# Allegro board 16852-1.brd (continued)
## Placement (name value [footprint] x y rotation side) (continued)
C5542  SCD1U50V3KX-GP  [C603H36]  69.88 87.03 180 top
C5617  SCD01U50V2KX-1GP  [C402H22]  264.54 35.04 0 top
C5618  SCD01U50V2KX-1GP  [C402H22]  263.65 35.04 0 top
C5619  SCD01U50V2KX-1GP  [C402H22]  261.75 35.04 180 top
C5620  SCD01U50V2KX-1GP  [C402H22]  262.64 35.04 180 top
C5621  SC1U10V2KX-1GP  [C402H22]  261.11 29.2 90 bottom
C5622  SC1U10V2KX-1GP  [C402H22]  261.11 33.77 270 bottom
C5623  SC1U10V2KX-1GP  [C402H22]  265.18 32.62 90 bottom
C5701  SCD1U16V2KX-3GP  [C402H22]  22.61 68.57 90 bottom
C5702  SCD1U16V2KX-3GP  [C402H22]  17.4 79.61 90 top
C5703  SCD1U16V2KX-3GP  [C402H22]  22.61 69.45 90 bottom
C5704  SCD1U16V2KX-3GP  [C402H22]  22.61 67.68 90 bottom
C5705  SCD1U16V2KX-3GP  [C402H22]  22.43 65.29 90 bottom
C5706  SCD1U16V2KX-3GP  [C402H22]  22.43 66.18 90 bottom
C5707  SCD1U16V2KX-3GP  [C402H22]  22.43 64.27 90 bottom
C5708  SCD1U16V2KX-3GP  [C402H22]  22.43 63.38 90 bottom
C5709  SCD1U16V2KX-3GP  [C402H22]  22.61 70.34 90 bottom
C5710  SCD1U16V2KX-3GP  [C402H22]  17.4 78.73 90 top
C6001  SCD1U16V2KX-3GP  [C402H22]  258.7 30.47 0 bottom
C6002  SC10U6D3V3MX-GP  [C603H38]  258.44 25.77 0 top
C6003  SCD01U50V2KX-1GP  [C402H22]  262 26.15 0 top
C6004  SCD01U50V2KX-1GP  [C402H22]  262.89 26.15 0 top
C6005  SCD01U50V2KX-1GP  [C402H22]  263.78 26.15 0 top
C6006  SCD01U50V2KX-1GP  [C402H22]  264.67 26.15 0 top
C6007  SCD1U16V2KX-3GP  [C402H22]  259.71 19.87 270 top
C6008  SC4D7U6D3V3KX-GP  [C603H36]  259.59 21.8 270 top
C6009  SC4D7U6D3V3KX-GP  [C603H36]  259.59 23.07 270 top
C6010  SCD1U16V2KX-3GP  [C402H22]  246.76 23.99 0 bottom
C6011  SC10U6D3V3MX-GP  [C603H38]  247.27 21.58 180 bottom
C6012  SCD1U16V2KX-3GP  [C402H22]  248.59 16.9 90 bottom
C6013  SC4D7U6D3V3KX-GP  [C603H36]  248.41 18.02 90 bottom
C6014  SC4D7U6D3V3KX-GP  [C603H36]  248.41 19.42 90 bottom
C6107  SCD1U16V2KX-3GP  [C402H22]  36.63 51.57 270 top
C6108  SC4D7U6D3V3KX-GP  [C603H36]  46.71 58.51 0 top
C6109  SCD1U16V2KX-3GP  [C402H22]  37.39 65.8 270 top
C6110  SC470P50V2KX-3GP  [C402H22]  37.39 66.69 270 top
C6111  SC470P50V2KX-3GP  [C402H22]  36.63 50.68 270 top
C6112  SC10U6D3V3MX-GP  [C603H38]  45.44 58.51 0 top
C6113  SC2200P50V2KX-2GP  [C402H22]  47.73 63.23 180 top
C6201  SCD1U16V2KX-3GP  [C402H22]  94.23 124.98 180 top
C6202  SCD1U16V2KX-3GP  [C402H22]  93.34 124.98 180 top
C6203  SCD1U16V2KX-3GP  [C402H22]  89.74 102.78 180 top
C6204  SCD1U16V2KX-3GP  [C402H22]  98.04 117.76 90 top
C6205  SCD1U16V2KX-3GP  [C402H22]  98.04 116.88 90 top
C6206  SC2200P50V2KX-2GP  [C402H22]  89.74 107.55 180 top
C6207  SCD1U16V2KX-3GP  [C402H22]  100.58 113.4 90 top
C6208  SCD1U16V2KX-3GP  [C402H22]  100.58 112.51 90 top
C6306  SC22P50V2JN-4GP  [C402H22]  85.09 107.94 270 top
C6501  SCD1U16V2KX-3GP  [C402H22]  185.17 49.9 0 bottom
C6502  SCD1U16V2KX-3GP  [C402H22]  183.51 54.72 0 bottom
C6503  SCD1U16V2KX-3GP  [C402H22]  195.58 17.51 270 bottom
C6504  SCD1U16V2KX-3GP  [C402H22]  171.07 11.42 180 top
C6701  SCD1U16V2KX-3GP  [C402H22]  104.88 4.63 90 bottom
C6702  SCD1U16V2KX-3GP  [C402H22]  104.88 5.45 90 bottom
C6703  SC10U6D3V3MX-GP  [C603H38]  110.06 5.85 0 top
C7001  SCD047U16V2KX-1-GP  [C402H22]  211.71 39.61 90 top
C7002  SCD1U16V2KX-3GP  [C402H22]  208.23 45.55 270 top
C7301  SCD22U10V2KX-1GP  [C402H22]  156.34 73.26 270 top
C7302  SCD22U10V2KX-1GP  [C402H22]  156.34 72.38 270 top
C7303  SCD22U10V2KX-1GP  [C402H22]  156.24 71.54 270 top
C7304  SCD22U10V2KX-1GP  [C402H22]  156.24 70.65 270 top
C7305  SCD22U10V2KX-1GP  [C402H22]  155.19 75.17 270 top
C7306  SCD22U10V2KX-1GP  [C402H22]  155.19 74.28 270 top
C7307  SCD22U10V2KX-1GP  [C402H22]  155.19 77.46 270 top
C7308  SCD22U10V2KX-1GP  [C402H22]  155.19 78.34 270 top
C7609  SC47P50V2JN-3GP  [C402H22]  154.74 76.19 270 bottom
C7710  SCD1U16V2KX-3GP  [C402H22]  180.09 72.88 180 top
C7711  SC1U10V2KX-1GP  [C402H22]  180.97 72.88 180 top
C7713  SC10U6D3V3MX-GP  [C603H38]  182.63 72.38 0 top
C7714  SCD1U16V2KX-3GP  [C402H22]  178.69 71.26 90 top
C7715  SC1U10V2KX-1GP  [C402H22]  178.71 72.1 90 top
C7801  SC1U10V2KX-1GP  [C402H22]  162.15 84.08 0 bottom
C7802  SC100P50V2JN-3GP  [C402H22]  198.12 107.17 270 bottom
C7805  SC1U10V2KX-1GP  [C402H22]  166.18 83.66 90 top
C7821  SCD1U16V2KX-3GP  [C402H22]  191.95 83.86 270 bottom
C7822  SCD1U16V2KX-3GP  [C402H22]  183.18 84.31 0 top
C7901  SC5D6P50V2CN-1GP  [C402H22]  160.5 69.53 0 bottom
C7903  SC5D6P50V2CN-1GP  [C402H22]  160.5 67.83 180 bottom
C7904  SC1U10V2KX-1GP  [C402H22]  176.91 71.49 90 top
C7918  SCD082U16V2KX-GP  [C402H22]  171.58 74.53 180 top
C7919  SCD68U16V3KX-GP-U  [C603H36]  171.7 72.12 270 top
C7920  SCD68U16V3KX-GP-U  [C603H36]  184.82 78.92 0 top
C7921  SCD01U50V2KX-1GP  [C402H22]  173.48 71.77 0 top
C8001  SC10U6D3V3MX-GP  [C603H38]  173.23 90.66 90 top
C8002  SC10U6D3V3MX-GP  [C603H38]  203.96 90.41 0 bottom
C8003  SC1U10V2KX-1GP  [C402H22]  175.64 90.54 270 top
C8004  SC1U10V2KX-1GP  [C402H22]  175.64 89.65 270 top
C8005  SC1U10V2KX-1GP  [C402H22]  178.56 90.54 90 top
C8006  SC1U10V2KX-1GP  [C402H22]  172.97 84.82 90 top
C8007  SCD1U16V2KX-3GP  [C402H22]  179.96 90.16 180 top
C8008  SC1U10V2KX-1GP  [C402H22]  176.91 72.38 90 top
C8009  SC1U10V2KX-1GP  [C402H22]  181.99 87.11 90 top
C8010  SC10U6D3V3MX-GP  [C603H38]  170.61 81.29 0 top
C8011  SCD1U16V2KX-3GP  [C402H22]  169.14 81.8 270 top
C8012  SCD1U16V2KX-3GP  [C402H22]  173.17 83.18 90 top
C8013  SC1U10V2KX-1GP  [C402H22]  169.57 84.29 270 top
C8014  SCD01U50V2KX-1GP  [C402H22]  182.5 89.14 0 top
C8015  SC1U10V2KX-1GP  [C402H22]  169.14 82.61 270 top
C8016  SC10U6D3V3MX-GP  [C603H38]  172.94 82.13 90 top
C8017  SC1U10V2KX-1GP  [C402H22]  175.05 78.11 90 top
C8018  SC1U10V2KX-1GP  [C402H22]  175.03 83.49 270 top
C8019  SC1U10V2KX-1GP  [C402H22]  180.63 82.2 90 top
C8020  SC1U10V2KX-1GP  [C402H22]  179.13 82.73 0 top
C8021  SC1U10V2KX-1GP  [C402H22]  180.84 80.96 270 top
C8022  SC1U10V2KX-1GP  [C402H22]  175.01 79.77 180 top
C8023  SC1U10V2KX-1GP  [C402H22]  175.03 81.02 270 top
C8024  SC1U10V2KX-1GP  [C402H22]  176.31 78.68 180 top
C8025  SC1U10V2KX-1GP  [C402H22]  176.68 81.84 180 top
C8026  SC1U10V2KX-1GP  [C402H22]  180.84 80.15 270 top
C8027  SC1U10V2KX-1GP  [C402H22]  178.31 81.83 180 top
C8028  SC1U10V2KX-1GP  [C402H22]  183.11 81.3 90 top
C8029  SC1U10V2KX-1GP  [C402H22]  183.13 80.47 90 top
C8030  SC1U10V2KX-1GP  [C402H22]  191.9 68.92 0 bottom
C8031  SC1U10V2KX-1GP  [C402H22]  170.18 86.47 270 top
C8032  SC1U10V2KX-1GP  [C402H22]  170.33 85.1 270 top
C8033  SC1U10V2KX-1GP  [C402H22]  175.01 87.49 180 top
C8034  SC1U10V2KX-1GP  [C402H22]  178.18 87.11 270 top
C8035  SC1U10V2KX-1GP  [C402H22]  173.36 79.84 180 top
C8036  SC1U10V2KX-1GP  [C402H22]  172.53 79.84 180 top
C8037  SC1U10V2KX-1GP  [C402H22]  189.92 64.55 0 top
C8038  SC10U6D3V3MX-GP  [C603H38]  198.12 64.5 0 top
C8039  SC10U6D3V3MX-GP  [C603H38]  185.93 64.5 180 bottom
C8040  SC10U6D3V3MX-GP  [C603H38]  188.72 64.5 180 bottom
C8041  SC10U6D3V3MX-GP  [C603H38]  196.85 64.5 0 top
C8042  SC1U10V2KX-1GP  [C402H22]  178.69 88.38 180 top
C8043  SC10U6D3V3MX-GP  [C603H38]  199.36 88.53 180 bottom
C8044  SC10U6D3V3MX-GP  [C603H38]  200.66 88.53 180 bottom
C8045  SC1U10V2KX-1GP  [C402H22]  198.3 88.3 180 bottom
C8046  SCD1U16V2KX-3GP  [C402H22]  174.19 79.77 180 top
C8047  SCD1U16V2KX-3GP  [C402H22]  174.96 81.85 270 top
C8048  SC1U10V2KX-1GP  [C402H22]  175.03 82.67 270 top
C8049  SC1U10V2KX-1GP  [C402H22]  179.75 78.31 90 top
C8050  SC1U10V2KX-1GP  [C402H22]  177.49 81.83 180 top
C8051  SC4D7U6D3V3KX-GP  [C603H36]  194.31 64.5 0 top
C8052  SC4D7U6D3V3KX-GP  [C603H36]  195.58 64.5 0 top
C8053  SC10U6D3V3MX-GP  [C603H38]  200.71 91.04 0 bottom
C8054  SC1U10V2KX-1GP  [C402H22]  199.67 90.56 0 bottom
C8055  SC1U10V2KX-1GP  [C402H22]  183.79 86.5 90 top
C8056  SCD1U16V2KX-3GP  [C402H22]  162.56 81.98 90 bottom
C8057  SC1U10V2KX-1GP  [C402H22]  172.9 81.09 90 top
C8058  SC1U10V2KX-1GP  [C402H22]  192.15 64.63 180 bottom
C8059  SC1U10V2KX-1GP  [C402H22]  191.26 64.63 180 bottom
C8060  SC1U10V2KX-1GP  [C402H22]  191.03 68.92 0 bottom
C8061  SC1U10V2KX-1GP  [C402H22]  190.73 64.55 0 top
C8062  SC1U10V2KX-1GP  [C402H22]  180.89 83.49 90 top
C8063  SC10U6D3V3MX-GP  [C603H38]  178.32 79.87 270 top
C8064  SC10U6D3V3MX-GP  [C603H38]  187.32 64.5 180 bottom
C8065  SC1U10V2KX-1GP  [C402H22]  169.13 83.45 270 top
C8066  SC22U6D3V3MX-1-GP  [C603H40]  193.04 64.5 0 top
C8129  SC1U10V2KX-1GP  [C402H22]  172.16 104.23 180 top
C8130  SC1U10V2KX-1GP  [C402H22]  161.8 116.95 270 bottom
C8131  SC1U10V2KX-1GP  [C402H22]  157.1 113.52 90 bottom
C8132  SC1U10V2KX-1GP  [C402H22]  157.1 115.05 90 bottom
C8133  SC10U6D3V3MX-GP  [C603H38]  177.93 121.91 0 bottom
C8134  SC10U6D3V3MX-GP  [C603H38]  156.97 108.44 90 bottom
C8135  SC1U10V2KX-1GP  [C402H22]  157.02 102.07 90 bottom
C8136  SC1U10V2KX-1GP  [C402H22]  157.1 102.47 270 top
C8137  SC1U10V2KX-1GP  [C402H22]  157.1 101.08 270 top
C8138  SC1U10V2KX-1GP  [C402H22]  184.91 117.08 270 bottom
C8139  SC1U10V2KX-1GP  [C402H22]  168.4 116.95 90 bottom
C8140  SC10U6D3V3MX-GP  [C603H38]  156.97 106.61 90 bottom
C8141  SC10U6D3V3MX-GP  [C603H38]  179.83 121.91 0 bottom
C8142  SC1U10V2KX-1GP  [C402H22]  157.1 103.87 270 top
C8143  SC1U10V2KX-1GP  [C402H22]  157.1 105.27 270 top
C8144  SC1U10V2KX-1GP  [C402H22]  157.1 106.67 270 top
C8145  SC1U10V2KX-1GP  [C402H22]  157.1 108.06 270 top
C8146  SCD01U50V2KX-1GP  [C402H22]  172.34 106.92 90 top
C8147  SCD1U16V2KX-3GP  [C402H22]  156.97 109.84 90 bottom
C8148  SC1U10V2KX-1GP  [C402H22]  195.58 113.22 270 bottom
C8149  SCD1U16V2KX-3GP  [C402H22]  172.57 113.6 270 bottom
C8150  SCD1U16V2KX-3GP  [C402H22]  172.34 112.25 90 top
C8151  SCD1U16V2KX-3GP  [C402H22]  172.57 114.46 270 bottom
C8152  SCD1U16V2KX-3GP  [C402H22]  156.97 101 90 bottom
C8153  SC1U10V2KX-1GP  [C402H22]  172.62 112.51 270 bottom
C8154  SCD1U16V2KX-3GP  [C402H22]  172.34 106.03 90 top
C8155  SCD1U16V2KX-3GP  [C402H22]  171.65 116.95 270 bottom
C8156  SCD1U16V2KX-3GP  [C402H22]  157 103.13 90 bottom
C8157  SCD1U16V2KX-3GP  [C402H22]  157 105.27 90 bottom
C8158  SC1U10V2KX-1GP  [C402H22]  157.02 104.2 90 bottom
C8201  SC1U10V2KX-1GP  [C402H22]  179.58 115.05 90 bottom
C8202  SC1U10V2KX-1GP  [C402H22]  190.37 117.08 90 bottom
C8203  SC1U10V2KX-1GP  [C402H22]  195.45 104.76 270 bottom
C8204  SC1U10V2KX-1GP  [C402H22]  179.81 116.98 180 bottom
C8205  SC10U6D3V3MX-GP  [C603H38]  195.58 116.62 270 bottom
C8206  SC10U6D3V3MX-GP  [C603H38]  195.58 114.79 270 bottom
C8207  SC1U10V2KX-1GP  [C402H22]  195.45 104.51 90 top
C8208  SC1U10V2KX-1GP  [C402H22]  195.45 106.03 270 bottom
C8209  SC1U10V2KX-1GP  [C402H22]  195.45 105.78 90 top
C8210  SC1U10V2KX-1GP  [C402H22]  195.45 107.05 90 top
C8211  SC1U10V2KX-1GP  [C402H22]  195.45 103.24 90 top
C8212  SC1U10V2KX-1GP  [C402H22]  195.45 111.11 90 top
C8213  SC10U6D3V3MX-GP  [C603H38]  195.45 112.89 90 top
C8214  SC10U6D3V3MX-GP  [C603H38]  195.45 114.69 90 top
C8215  SC1U10V2KX-1GP  [C402H22]  179.71 101.33 270 top
C8216  SC1U10V2KX-1GP  [C402H22]  195.45 101.97 90 top
C8217  SC1U10V2KX-1GP  [C402H22]  172.72 102.22 90 top
C8218  SC1U10V2KX-1GP  [C402H22]  179.58 112.63 90 bottom
C8219  SC1U10V2KX-1GP  [C402H22]  172.34 110.09 180 bottom
C8220  SC1U10V2KX-1GP  [C402H22]  179.83 104.13 180 bottom
C8221  SCD01U50V2KX-1GP  [C402H22]  179.96 108.72 270 top
C8222  SCD1U16V2KX-3GP  [C402H22]  179.96 113.14 270 top
C8223  SCD1U16V2KX-3GP  [C402H22]  179.96 112.25 270 top
C8224  SCD1U16V2KX-3GP  [C402H22]  179.81 109.23 90 bottom
C8225  SCD1U16V2KX-3GP  [C402H22]  179.81 110.09 90 bottom
C8226  SCD1U16V2KX-3GP  [C402H22]  179.96 103.36 270 top
C8227  SCD1U16V2KX-3GP  [C402H22]  193.8 117.92 270 bottom
C8228  SCD1U16V2KX-3GP  [C402H22]  179.96 106.03 270 top
C8229  SCD1U16V2KX-3GP  [C402H22]  172.57 115.91 270 bottom
C8230  SCD1U16V2KX-3GP  [C402H22]  195.66 111.19 270 bottom
C9101  SC2200P50V2KX-2GP  [C402H22]  251.71 33.64 0 bottom
C9102  SCD1U16V2KX-3GP  [C402H22]  250.82 33.64 0 bottom
C9103  SCD033U16V2KX-GP  [C402H22]  249.43 34.28 270 top
C9104  SC2200P50V2KX-2GP  [C402H22]  249.94 33.64 0 bottom
C9105  SC4D7U6D3V3KX-GP  [C603H36]  250.82 32.12 90 bottom
C9106  SC4D7U6D3V3KX-GP  [C603H36]  250.57 26.53 90 bottom
C9107  SC10U6D3V3MX-GP  [C603H38]  89.71 5.98 90 top
C9108  SCD1U16V2KX-3GP  [C402H22]  82.32 4 0 bottom
C9109  SCD1U16V2KX-3GP  [C402H22]  86.36 4.94 90 bottom
C9110  SCD1U16V2KX-3GP  [C402H22]  85.55 8.06 90 bottom
C9111  SCD1U16V2KX-3GP  [C402H22]  78.99 4.68 90 bottom
C9112  SCD1U16V2KX-3GP  [C402H22]  243.41 32.93 270 top
C9113  SCD1U16V2KX-3GP  [C402H22]  250.95 27.67 90 bottom
C9114  SC4D7U6D3V3KX-GP  [C603H36]  250.82 30.85 90 bottom
C9115  SCD1U16V2KX-3GP  [C402H22]  243.71 33.77 90 top
C9116  SCD1U16V2KX-3GP  [C402H22]  247.01 30.54 90 bottom
C9117  SCD1U16V2KX-3GP  [C402H22]  254.33 29.91 270 bottom
C9201  SCD1U16V2KX-3GP  [C402H22]  278 20.94 180 bottom
C9202  SC1U10V2KX-1GP  [C402H22]  278.89 20.94 180 bottom
C9601  SCD1U16V2KX-3GP  [C402H22]  75.82 77.84 180 bottom
C9603  SC1U10V2KX-1GP  [C402H22]  67.82 72.12 90 bottom
C9901  SCD1U16V2KX-3GP  [C402H22]  63.78 100.47 180 top
C9902  SCD1U16V2KX-3GP  [C402H22]  59.44 83.3 180 bottom
C9903  SCD1U16V2KX-3GP  [C402H22]  59.79 100.01 180 top
C9904  SCD1U16V2KX-3GP  [C402H22]  58.55 83.3 180 bottom
C9905  SCD1U16V2KX-3GP  [C402H22]  59.31 88.5 90 top
CPU1  SKYLAKE-U-GP  [BGA1356M4224-U2H52]  111.62 75.4 0 bottom
D401  RB751V-40H-GP  [SOD323AKH38]  140.08 53.45 180 bottom
D1702  BAW56-9-GP  [SOT-23-10H44]  152.65 62.72 0 top
D1703  RB751V-40H-GP  [SOD323AKH38]  181.86 50.15 180 bottom
D2402  RB751V-40H-GP  [SOD323AKH38]  211.96 43.42 0 top
D2403  RB751V-40H-GP  [SOD323AKH38]  214.12 40.63 180 top
D2405  RB751V-40H-GP  [SOD323AKH38]  181.48 8.62 270 bottom
D2501  BAS40C-2-GP  [SOT-23-9H44]  230 39.1 0 bottom
D2601  RB551V30-GP  [SOD323AKH38]  214 46.47 270 top
D2701  BAT54C-7-F-3-GP  [SOT23-2D4-312H48]  21.54 18.35 270 bottom
D4001  RB751V-40H-GP  [SOD323AKH38]  54.58 36.64 90 top
D4002  BAS16-6-GP  [SOT23-2D4-312H44]  197.08 10.17 180 bottom
D5501  RB551V30-GP  [SOD323AKH38]  78.36 99.43 270 top
D5502  BAT54C-7-F-3-GP  [SOT23-2D4-312H48]  37.21 71.23 270 top
D5503  BAT54C-7-F-3-GP  [SOT23-2D4-312H48]  51.18 69.2 0 top
D5701  BAW56-9-GP  [SOT-23-10H44]  24.89 79.18 0 bottom
D5702  AP2331SA-7-GP  [SOT23-2D4-312H48]  17.48 79.41 0 bottom
D6101  RB751V-40H-GP  [SOD323AKH38]  42.04 58.02 90 top
D6102  RB751V-40H-GP  [SOD323AKH38]  41.02 51.29 270 top
D6201  RB751V-40H-GP  [SOD323AKH38]  87.12 101.53 270 top
D6202  RB751V-40H-GP  [SOD323AKH38]  87.12 99.43 270 top
D7601  BAW56-5-GP  [SOT-23-9H44]  147.96 78.34 90 bottom
D8601  BAT54C-7-F-3-GP  [SOT23-2D4-312H48]  156.39 56.12 0 top
D8602  BAT54C-7-F-3-GP  [SOT23-2D4-312H48]  205.87 114.03 270 bottom
DB1  FOX-CON10-S1-GP  [HS81100]  290.12 27.65 90 top
DB2  ACES-CON4-37-GP  [88459-047N]  211.2 103.5 270 bottom
DB3  ACES-CON6-58-GP  [50696-00601-001]  286.26 42.91 90 top
DCIN1  ACES-CON6-63-GP  [50458-00601-W01]  48.4 112.5 90 bottom
DM1  DDR4-260P-9-GP-U  [80886-1021-U]  78.1 15.5 0 bottom
DM2  DDR4-260P-9-GP-U  [80886-1021-U]  155.1 15.5 0 bottom
EC1001  SC1U10V2KX-1GP  [C402H22]  99.19 52.84 270 top
EC1002  SCD1U25V2KX-GP  [C402H22]  115.14 68.18 180 top
EC1004  SC1U10V2KX-1GP  [C402H22]  118.75 65.14 90 top
EC1059  SC10U6D3V3MX-GP  [C603H38]  68.45 11.29 0 top
EC1060  SC10U6D3V3MX-GP  [C603H38]  62.61 28.05 180 top
EC1062  SC10U6D3V3MX-GP  [C603H38]  87.76 19.29 90 top
EC1063  SC10U6D3V3MX-GP  [C603H38]  71.75 19.16 270 top
EC1220  SCD1U25V2KX-GP  [C402H22]  62.61 19.16 0 top
EC1701  AZ5725-01FDR7G-GP  [SOD882-10D6-1H20]  85.85 87.49 180 bottom
EC1702  AZ5725-01FDR7G-GP  [SOD882-10D6-1H20]  132.21 92.64 0 bottom
EC1703  AZ5725-01FDR7G-GP  [SOD882-10D6-1H20]  153.67 74.79 180 bottom
EC1704  AZ5725-01FDR7G-GP  [SOD882-10D6-1H20]  70.56 87.23 90 bottom
EC1705  AZ5725-01FDR7G-GP  [SOD882-10D6-1H20]  50.8 28.43 90 top
EC1706  SC1KP50V2KX-1GP  [C402H22]  132.26 94.04 90 bottom
EC1707  SCD1U16V2KX-3GP  [C402H22]  158.12 71.23 270 bottom
EC1708  SCD01U50V2KX-L-GP  [C402H22]  91.82 91.58 270 bottom
EC1709  AZ5725-01FDR7G-GP  [SOD882-10D6-1H20]  89.15 94.09 90 bottom
EC1710  SC22P50V2JN-4GP  [C402H22]  84.07 87.49 0 bottom
EC1711  SCD1U16V2KX-3GP  [C402H22]  150.75 64.63 270 bottom
EC1712  SCD1U16V2KX-3GP  [C402H22]  152.15 70.22 270 bottom
EC1713  SC22P50V2JN-4GP  [C402H22]  119.2 52 90 bottom
EC1714  AZ5725-01FDR7G-GP  [SOD882-10D6-1H20]  120.9 52.06 90 bottom
EC1715  AZ5725-01FDR7G-GP  [SOD882-10D6-1H20]  91.82 92.44 270 bottom
EC1716  SC2D2U10V2KX-GP  [C402H22]  150.11 89.01 270 bottom
EC1801  SC10P50V2JN-4GP  [C402H22]  132.64 55.46 180 bottom
EC1802  SC10P50V2JN-4GP  [C402H22]  131.37 55.05 270 bottom
EC1803  SC4D7P50V2BN-GP  [C402H22]  123.44 53.58 0 bottom
EC1805  SCD1U16V2KX-3GP  [C402H22]  135 91.68 0 bottom
EC1806  SCD1U16V2KX-3GP  [C402H22]  133.35 47.86 0 top
EC1807  SCD1U16V2KX-3GP  [C402H22]  137.82 46.75 270 bottom
EC1808  SCD1U16V2KX-3GP  [C402H22]  140.77 45.96 180 top
EC1901  SC10P50V2JN-4GP  [C402H22]  113.97 48.42 270 bottom
EC1903  SC1KP50V2KX-1GP  [C402H22]  130.25 91.55 0 bottom
EC2001  SC1500P50V2KX-2GP  [C402H22]  128.27 70.98 270 top
EC2002  SC1KP50V2KX-1GP  [C402H22]  141.6 79.74 270 bottom
EC2401  SCD1U16V2KX-3GP  [C402H22]  210.03 34.4 180 bottom
EC2501  SC4D7P50V2BN-GP  [C402H22]  144.53 51.7 270 top
EC2502  SC4D7P50V2BN-GP  [C402H22]  154.81 49.64 270 bottom
EC2503  SC10P50V2JN-4GP  [C402H22]  144.2 52.11 180 bottom
EC2504  SC4D7P50V2BN-GP  [C402H22]  171.35 50.56 270 bottom
EC2505  SC10P50V2JN-4GP  [C402H22]  158.62 48.5 90 bottom
EC2506  SC4D7P50V2BN-GP  [C402H22]  170.31 47.61 270 bottom
EC2507  SC4D7P50V2BN-GP  [C402H22]  92.13 6.67 270 top
EC2508  SC10P50V2JN-4GP  [C402H22]  102.16 5.14 90 top
EC2509  SC4D7P50V2BN-GP  [C402H22]  102.16 4.25 90 top
EC2601  SCD1U16V2KX-3GP  [C402H22]  213.36 49.39 90 top
EC2602  SC10P50V2JN-4GP  [C402H22]  214.5 43.42 90 top
EC2603  SC2200P50V2KX-2GP  [C402H22]  213.36 50.23 90 top
EC2701  SC10P50V2JN-4GP  [C402H22]  27.05 16.5 90 top
EC2703  SCD1U25V2KX-GP  [C402H22]  19.58 16.68 180 top
EC2704  SC1KP50V2KX-1GP  [C402H22]  31.98 4.46 90 top
EC2705  SCD1U25V2KX-GP  [C402H22]  21.08 11.03 270 bottom
EC2706  SC1KP50V2KX-1GP  [C402H22]  31.98 5.29 90 top
EC2707  SC1KP50V2KX-1GP  [C402H22]  15.94 19.69 0 bottom
EC2708  SCD1U16V2KX-3GP  [C402H22]  25.02 20.81 180 top
EC2709  SCD1U16V2KX-3GP  [C402H22]  24.13 20.81 180 top
EC2723  SC22P50V2JN-4GP  [C402H22]  26.29 19.16 90 top
EC2901  SC1KP50V2KX-1GP  [C402H22]  31.52 13.62 180 top
EC2902  SC1KP50V2KX-1GP  [C402H22]  31.5 16.67 0 top
EC2903  SC1KP50V2KX-1GP  [C402H22]  33.02 12.74 0 top
EC2904  SC1KP50V2KX-1GP  [C402H22]  33.02 10.4 180 top
EC2905  SC100P50V2JN-3GP  [C402H22]  17.12 10.88 270 top
EC2906  SC100P50V2JN-3GP  [C402H22]  17.78 14.08 90 bottom
EC2907  SC100P50V2JN-3GP  [C402H22]  23.5 2.27 270 bottom
EC2908  SC100P50V2JN-3GP  [C402H22]  22.67 3.55 0 bottom
EC2909  SC33P50V2JN-3GP  [C402H22]  38.86 10.65 90 top
EC2910  SC33P50V2JN-3GP  [C402H22]  38.99 12.3 90 top
EC2911  SC33P50V2JN-3GP  [C402H22]  37.59 14.59 90 top
EC2912  SC33P50V2JN-3GP  [C402H22]  37.59 13.7 90 top
EC3101  SC10P50V2JN-4GP  [C402H22]  28.83 83.04 0 bottom
EC3102  SC10P50V2JN-4GP  [C402H22]  28.83 84.82 180 bottom
EC3103  SC10P50V2JN-4GP  [C402H22]  28.83 86.6 0 bottom
EC3104  SC10P50V2JN-4GP  [C402H22]  28.83 88.38 180 bottom
EC3105  SC10P50V2JN-4GP  [C402H22]  28.7 91.55 0 bottom
EC3106  SC10P50V2JN-4GP  [C402H22]  28.7 93.33 180 bottom
EC3107  SC10P50V2JN-4GP  [C402H22]  28.7 95.11 0 bottom
EC3108  SC10P50V2JN-4GP  [C402H22]  28.7 96.89 180 bottom
EC3618  SCD1U16V2KX-3GP  [C402H22]  19.94 29.2 0 top
EC3619  SCD1U16V2KX-3GP  [C402H22]  21.41 58.2 270 bottom
EC3701  SCD1U16V2KX-3GP  [C402H22]  278 31.99 90 bottom
EC4001  SCD1U16V2KX-3GP  [C402H22]  151.89 84.44 270 bottom
EC4301  SC10U25V5KX-GP  [C805H56]  53.67 113.52 270 top
EC4302  SCD1U25V2KX-GP  [C402H22]  53.59 110.22 270 top
EC4303  SCD1U25V2KX-GP  [C402H22]  53.59 111.11 270 top
EC4304  SCD1U25V2KX-GP  [C402H22]  53.59 112 270 top
EC4314  SCD1U25V2KX-GP  [C402H22]  231.27 32.12 90 top
EC5312  SC1KP50V2KX-L-1-GP  [C402H22]  201.93 25.82 90 bottom
EC5501  SC6P50V2CN-1GP  [C402H22]  47.75 74.79 90 top
EC5502  SC6P50V2CN-1GP  [C402H22]  45.97 74.79 270 top
EC5504  SC10P50V2JN-4GP  [C402H22]  72.64 89.77 90 bottom
EC5505  SCD1U25V2KX-GP  [C402H22]  71.83 87.77 0 top
EC5701  SC1U10V2KX-1GP  [C402H22]  17.02 75.8 90 top
EC5702  SC1KP50V2KX-1GP  [C402H22]  16.89 77.2 90 top
EC6001  SC1KP50V2KX-1GP  [C402H22]  265.94 25.77 0 bottom
EC6102  SC33P50V2JN-3GP  [C402H22]  33.17 57.74 90 top
EC6103  SC33P50V2JN-3GP  [C402H22]  33.17 58.56 90 top
EC6301  SC33P50V2JN-3GP  [C402H22]  84.07 105.4 90 top
EC6302  SC1U10V2KX-1GP  [C402H22]  81.66 109.71 180 top
EC6303  SC33P50V2JN-3GP  [C402H22]  80.77 104.38 90 top
EC6304  SC33P50V2JN-3GP  [C402H22]  83.82 107.43 0 top
EC6305  SC33P50V2JN-3GP  [C402H22]  79.25 109.71 180 top
EC6401  SC1KP50V2KX-1GP  [C402H22]  274.07 32.12 0 bottom
EC6402  SCD1U25V2KX-GP  [C402H22]  208.15 3.92 270 top
EC6403  SCD1U25V2KX-GP  [C402H22]  206.38 3.41 270 top
EC6404  SC1KP50V2KX-1GP  [C402H22]  274.45 33.39 270 bottom
EC6406  SCD1U16V2KX-3GP  [C402H22]  275.72 33.89 180 bottom
EC6501  SC33P50V2JN-3GP  [C402H22]  134.37 3.29 0 top
EC6502  SC33P50V2JN-3GP  [C402H22]  125.48 8.75 0 bottom
EC6503  SC33P50V2JN-3GP  [C402H22]  134.37 5.07 180 top
EC6504  SC33P50V2JN-3GP  [C402H22]  125.48 6.97 180 bottom
EC6505  SC33P50V2JN-3GP  [C402H22]  119.76 6.84 180 bottom
EC6506  SC33P50V2JN-3GP  [C402H22]  119.76 8.75 0 bottom
EC6507  SCD1U16V2KX-3GP  [C402H22]  169.62 44.56 0 top
EC7001  SCD1U16V2KX-3GP  [C402H22]  211.71 40.5 90 top
EC8536  SCD1U25V2KX-GP  [C402H22]  215.24 75.4 0 top
EC8537  SCD1U25V2KX-GP  [C402H22]  214.55 84.69 180 top
EC9201  SC22P50V2JN-4GP  [C402H22]  271.12 27.11 270 bottom
EC9202  SC22P50V2JN-4GP  [C402H22]  272.9 27.11 90 bottom
EC9203  SC1U10V2KX-1GP  [C402H22]  27.66 21.75 270 top
EC9701  SCD1U25V2KX-GP  [C402H22]  128.27 125.08 180 bottom
EC9702  SCD1U25V2KX-GP  [C402H22]  151.64 124.19 90 bottom
EC9703  SCD1U25V2KX-GP  [C402H22]  136.78 125.46 180 bottom
EC9704  SCD1U25V2KX-GP  [C402H22]  209.42 95.87 180 bottom
EC9705  SCD1U25V2KX-GP  [C402H22]  105.92 126.86 90 bottom
EC9707  SCD1U25V2KX-GP  [C402H22]  70.48 125.21 270 top
EC9710  SCD1U25V2KX-GP  [C402H22]  53.14 64.55 270 top
EC9712  SCD1U25V2KX-GP  [C402H22]  210.95 118.86 180 bottom
EC9714  SCD1U25V2KX-GP  [C402H22]  50.04 35.67 0 top
EC9715  SCD1U25V2KX-GP  [C402H22]  209.6 125 180 top
EC9716  SCD1U25V2KX-GP  [C402H22]  225.04 18.02 180 top
EC9717  SCD1U25V2KX-GP  [C402H22]  116.71 124.7 0 top
EC9718  SC1U10V2KX-1GP  [C402H22]  212.09 51.67 180 top
EC9719  SC1U10V2KX-1GP  [C402H22]  258.93 29.04 180 top
EC9720  SC1U10V2KX-1GP  [C402H22]  33.53 81.93 270 top
EC9721  SCD1U25V2KX-GP  [C402H22]  66.07 46.19 270 top
EC9722  SC1U10V2KX-1GP  [C402H22]  28.45 72.38 180 bottom
EC9724  SCD1U25V2KX-GP  [C402H22]  208.91 101.08 180 top
EC9725  SC1U10V2KX-1GP  [C402H22]  179.96 102.47 270 top
EC9726  SC1U50V3KX-GP  [C603H32]  226.19 17.77 180 top
EC9727  SC1U50V3KX-GP  [C603H32]  216.28 68.69 0 top
EC9728  SC1U50V3KX-GP  [C603H32]  153.29 126.35 180 top
EC9732  SC1U10V2KX-1GP  [C402H22]  51.67 8.08 90 bottom
EC9733  SC1U10V2KX-1GP  [C402H22]  204.83 6.11 180 bottom
EC9734  SC1U10V2KX-1GP  [C402H22]  160.58 59.12 180 bottom
EC9735  SCD1U25V2KX-GP  [C402H22]  240.16 31.48 180 bottom
EC9736  SC1U10V2KX-1GP  [C402H22]  141.94 82.92 270 bottom
EC9737  SC1U10V2KX-1GP  [C402H22]  194.92 10.02 180 top
EC9739  SCD1U25V2KX-GP  [C402H22]  21.08 12.05 270 bottom
EC9743  SCD1U25V2KX-GP  [C402H22]  23.94 7.22 0 bottom
EC9744  SCD1U25V2KX-GP  [C402H22]  24.77 7.22 0 bottom
EC9745  SC1KP50V2KX-1GP  [C402H22]  32 2.32 90 top
ED401  AZ5725-01FDR7G-GP  [SOD882-10D6-1H20]  93.9 94.93 90 bottom
ED502  AZ5725-01FDR7G-GP  [SOD882-10D6-1H20]  148.46 57.19 270 top
ED1217  AZ5725-01FDR7G-GP  [SOD882-10D6-1H20]  147.4 10.81 180 top
ED1302  AZ5725-01FDR7G-GP  [SOD882-10D6-1H20]  71.12 10.66 270 top
ED2901  AZ5125-02S-R7G-GP  [SOT23-2D4-312H46]  17.86 9.05 90 bottom
ED2902  AZ5125-02S-R7G-GP  [SOT23-2D4-312H46]  17.53 17.62 180 bottom
ED2903  AZ5125-02S-R7G-GP  [SOT23-2D4-312H46]  21.11 6.16 90 bottom
ED3201  AZ1043-04F-R7G-GP  [DFN10G2510H22]  40.13 83.55 0 bottom
ED3202  AZ1043-04F-R7G-GP  [DFN10G2510H22]  32.38 95.87 270 bottom
ED3601  AZ1043-04F-R7G-GP  [DFN10G2510H22]  17.53 51.8 270 bottom
ED3602  AZC099-04S-2-GP  [SOT-6H58]  18.11 57.29 90 bottom
ED3603  AZ1043-04F-R7G-GP  [DFN10G2510H22]  18.67 24.24 270 bottom
ED3604  AZC099-04S-2-GP  [SOT-6H58]  19.3 37.45 90 bottom
ED3701  AZC099-04S-2-GP  [SOT-6H58]  275.97 37.07 270 bottom
ED4304  LBAV99LT1G-1-GP  [SOT23-2D4-312H44]  239.14 36.05 270 bottom
ED4305  LBAV99LT1G-1-GP  [SOT23-2D4-312H44]  231.9 38.72 270 top
ED4306  LBAV99LT1G-1-GP  [SOT23-2D4-312H44]  231.88 34.73 0 top
ED5701  AOZ8808DI-05-1-GP  [SLP2510P8-1H24]  16.89 64.76 90 bottom
ED5702  AOZ8808DI-05-1-GP  [SLP2510P8-1H24]  16.89 69.07 90 bottom
ED5703  AOZ8808DI-05-1-GP  [SLP2510P8-1H24]  16.92 74.46 90 bottom
ED6001  AZ1045-04F-R7G-GP  [DFN10G2510H26]  264.92 21.7 0 top
ED6201  AZ1045-04F-R7G-GP  [DFN10G2510H26]  100.46 116.44 90 top
ED6301  IP4223CZ6-1-GP  [SOT-6H44]  80.77 106.79 90 top
ED6401  AZ5725-01FDR7G-GP  [SOD882-10D6-1H20]  274.95 32.12 0 bottom
ED9201  AZC099-04S-2-GP  [SOT-6H58]  270.21 24.24 90 top
EL2901  PBY160808T-121Y-GP  [L1608-UH38]  33.15 14.34 270 top
EL2902  PBY160808T-121Y-GP  [L1608-UH38]  33.15 15.61 270 top
EL2903  PBY160808T-121Y-GP  [L1608-UH38]  34.67 12.18 270 top
EL2904  PBY160808T-121Y-GP  [L1608-UH38]  34.67 10.4 270 top
EL3301  FILTER-4P-137-GP-U  [L125100-4P-4H28]  271.02 32.5 0 bottom
EL3601  FILTER-4P-137-GP-U  [L125100-4P-4H28]  22.02 56.35 180 bottom
EL3602  FILTER-4P-137-GP-U  [L125100-4P-4H28]  22.5 27.54 180 bottom
EL3701  FILTER-4P-137-GP-U  [L125100-4P-4H28]  271.02 34.78 0 bottom
EL4301  0R0805-PAD-2-GP-U  [0R0805-PAD-1-U]  53.67 117.33 270 top
EL4302  0R0805-PAD-2-GP-U  [0R0805-PAD-1-U]  53.67 115.43 270 top
EL4303  0R0805-PAD-2-GP-U  [0R0805-PAD-1-U]  48.92 108.98 270 top
EL4304  0R0805-PAD-2-GP-U  [0R0805-PAD-1-U]  48.92 107.12 270 top
EL5501  FILTER-4P-137-GP-U  [L125100-4P-4H28]  44.96 68.44 90 top
EL5503  AZC199-04S-R7G-GP  [SOT-6-1H58]  43.69 72.25 0 top
ER5701  150R2J-L1-GP-U  [R402H16]  18.8 68.18 180 bottom
ER5702  150R2J-L1-GP-U  [R402H16]  18.77 63.84 180 bottom
ER5703  150R2J-L1-GP-U  [R402H16]  18.8 69.96 180 bottom
ER5704  150R2J-L1-GP-U  [R402H16]  18.77 65.67 180 bottom
F5502  POLYSW-1D1A6V-9-GP-U  [POLYSW-2114H30]  38.48 74.41 270 top
F5503  POLYSW-1D1A24V-GP-U  [POLYSW-4633-UH43]  61.21 81.01 0 top
FAN1  ACES-CON4-17-GP-U1  [88631-00401-W01]  212.4 62.5 0 bottom
FAN261  AP2113MTR-G1-GP  [SOIC8H69]  210.82 48.25 0 bottom
FC701  SCD1U25V2KX-GP  [C402H22]  129.45 103.83 270 bottom
FC702  SCD1U25V2KX-GP  [C402H22]  106.96 82.08 270 top
FC703  SCD1U25V2KX-GP  [C402H22]  104.52 86.22 90 top
FC704  SCD1U25V2KX-GP  [C402H22]  104.19 70.8 90 top
FC705  SC470P50V2KX-L-GP  [C402H22]  111.05 65.36 180 top
FC706  SCD1U25V2KX-GP  [C402H22]  113.16 70.6 0 top
FC707  SCD1U25V2KX-GP  [C402H22]  138.33 102.17 270 bottom
FC708  SCD1U25V2KX-GP  [C402H22]  124.1 80.99 90 top
FC1001  SCD1U25V2KX-GP  [C402H22]  129.44 103.85 90 top
FC1002  SCD1U25V2KX-GP  [C402H22]  116.74 100.42 270 top
FC1003  SCD1U25V2KX-GP  [C402H22]  112.95 86.12 90 top
FC1004  SCD1U25V2KX-GP  [C402H22]  93.2 70.21 0 top
FC1005  SC470P50V2KX-L-GP  [C402H22]  54.1 19.42 0 top
FC1006  SC470P50V2KX-L-GP  [C402H22]  153.54 11.42 0 top
FC1301  SCD1U25V2KX-GP  [C402H22]  40.89 14.01 270 top
FC1901  SCD1U25V2KX-GP  [C402H22]  113.41 51.29 180 bottom
FC2401  SCD1U25V2KX-GP  [C402H22]  174.66 21.99 90 top
FC2402  SCD1U25V2KX-GP  [C402H22]  51.45 92.5 180 bottom
FC2403  SC470P50V2KX-L-GP  [C402H22]  32 50.91 180 top
FC2501  SCD1U25V2KX-GP  [C402H22]  145.01 52.11 180 bottom
FC2701  SCD1U25V2KX-GP  [C402H22]  26.29 20.05 270 top
FC4301  SCD1U25V2KX-GP  [C402H22]  69.49 112.66 180 top
FC4701  SCD1U25V2KX-GP  [C402H22]  120.75 122.62 90 bottom
FC4702  SCD1U25V2KX-GP  [C402H22]  109.47 86.3 0 top
FC4801  SCD1U25V2KX-GP  [C402H22]  106.76 117.36 90 bottom
FC5001  SCD1U25V2KX-GP  [C402H22]  135.41 120.61 270 bottom
FC5301  SCD1U25V2KX-GP  [C402H22]  44.91 21.65 270 top
FC5401  SCD1U25V2KX-GP  [C402H22]  51.66 7.2 90 bottom
FC5402  SCD1U25V2KX-GP  [C402H22]  50.04 3.54 90 bottom
FC5501  SC470P50V2KX-L-GP  [C402H22]  59.31 75.93 0 top
FC5502  SCD1U25V2KX-GP  [C402H22]  62.1 75.3 90 top
FC5503  SC470P50V2KX-L-GP  [C402H22]  44.45 78.98 90 top
FC6001  SCD1U25V2KX-GP  [C402H22]  185.17 56.21 90 bottom
FC6002  SCD1U25V2KX-GP  [C402H22]  234.17 33.82 90 bottom
FC6003  SC470P50V2KX-L-GP  [C402H22]  52.78 8.43 0 top
FC6004  SC470P50V2KX-L-GP  [C402H22]  259.71 20.76 270 top
FC6005  SC470P50V2KX-L-GP  [C402H22]  251.71 18.02 180 bottom
FC6101  SCD1U25V2KX-GP  [C402H22]  37.39 64.91 270 top
FC6201  SCD1U25V2KX-GP  [C402H22]  96.49 125.41 180 top
FC9701  SC470P50V2KX-L-GP  [C402H22]  205.69 72.43 90 top
FC9702  SCD1U25V2KX-GP  [C402H22]  204.11 124.6 270 top
FC9703  SC470P50V2KX-L-GP  [C402H22]  199.57 106.72 270 top
FC9704  SCD1U25V2KX-GP  [C402H22]  53.54 81.82 270 top
FC9705  SC470P50V2KX-L-GP  [C402H22]  25.22 80.71 0 top
FC9706  SCD1U25V2KX-GP  [C402H22]  51.08 94.93 180 bottom
FC9707  SCD1U25V2KX-GP  [C402H22]  112.83 3.95 0 bottom
FC9708  SCD1U25V2KX-GP  [C402H22]  264.29 34.25 180 bottom
FC9709  SCD1U25V2KX-GP  [C402H22]  40.67 80.12 90 top
FC9710  SC100P50V2JN-L-GP  [C402H22]  54.36 84.44 270 top
FC9711  SC100P50V2JN-L-GP  [C402H22]  169.29 11.42 180 top
FC9712  SC100P50V2JN-L-GP  [C402H22]  58.17 50.53 90 top
FC9713  SC100P50V2JN-L-GP  [C402H22]  115.7 9 0 bottom
FC9714  SC100P50V2JN-L-GP  [C402H22]  91.95 8.49 180 bottom
FC9715  SC100P50V2JN-L-GP  [C402H22]  66.04 8.37 180 bottom
FC9716  SC100P50V2JN-L-GP  [C402H22]  67.69 47.23 90 top
FC9717  SC470P50V2KX-L-GP  [C402H22]  105.92 126.86 270 top
FC9718  SC470P50V2KX-L-GP  [C402H22]  66.04 101.46 270 top
FC9719  SC470P50V2KX-L-GP  [C402H22]  58.55 73.26 90 top
FC9720  SC470P50V2KX-L-GP  [C402H22]  53.29 65.44 270 top
FC9721  SC470P50V2KX-L-GP  [C402H22]  51.05 76.82 270 top
FC9722  SC470P50V2KX-L-GP  [C402H22]  105.92 127.75 90 bottom
FC9723  SC470P50V2KX-L-GP  [C402H22]  128.27 125.08 0 top
FC9724  SC470P50V2KX-L-GP  [C402H22]  130.56 125.08 180 bottom
FC9725  SC470P50V2KX-L-GP  [C402H22]  135.94 125.61 180 bottom
FC9726  SC470P50V2KX-L-GP  [C402H22]  151.64 125.03 90 bottom
FC9727  SC470P50V2KX-L-GP  [C402H22]  57.15 73.01 270 bottom
FC9728  SC470P50V2KX-L-GP  [C402H22]  210.06 118.86 180 bottom
FC9729  SC470P50V2KX-L-GP  [C402H22]  208.58 95.86 180 bottom
FC9730  SC470P50V2KX-L-GP  [C402H22]  216.53 68.95 180 bottom
FC9731  SC470P50V2KX-L-GP  [C402H22]  218.57 45.58 90 bottom
FC9732  SC470P50V2KX-L-GP  [C402H22]  147.19 127.24 90 top
FC9733  SC470P50V2KX-L-GP  [C402H22]  152.15 126.35 180 top
FC9734  SC470P50V2KX-L-GP  [C402H22]  43.94 46.98 270 top
FC9735  SC470P50V2KX-L-GP  [C402H22]  209.8 101.08 180 top
FC9736  SC470P50V2KX-L-GP  [C402H22]  224.28 41.01 90 top
FC9737  SC470P50V2KX-L-GP  [C402H22]  230.76 6.39 0 top
FC9738  SC470P50V2KX-L-GP  [C402H22]  51.05 88.38 270 bottom
FPR1  PTWO-CON6-21-GP  [196415-06031-3]  277.9 19.7 90 top
G1801  GAP-OPEN  [CON2O-U]  137.77 48.8 90 bottom
G6401  GAP-OPEN  [CON2O-U]  274.19 30.47 0 bottom
G6402  GAP-OPEN  [CON2O-U]  275.72 30.47 0 bottom
GPU1  JET-XT-S3-GP  [BGA631M23H82]  176.92 80.8 180 bottom
H1  HOLE335R115-GP  [HOLE335R115]  165.3 123 0 top
H2  HOLE335R115-GP  [HOLE335R115]  186.15 123 0 top
H3  HOLE335R115-GP  [HOLE335R115]  19.9 44 0 top
H4  HOLE256R115-GP  [HOLE256R115]  251.4 13 0 top
H5  HOLE335R115-GP  [HOLE335R115]  289.4 52.5 180 bottom
H6  HT85BE95R46-D-5-GP  [HT85BE95R46-D-5]  35 88.75 0 top
HCPU1  HOLE197R166-1-GP  [HOLE197R166]  80.9 91.8 0 top
HCPU2  HOLE197R166-1-GP  [HOLE197R166]  138.27 91.8 0 top
HCPU3  HOLE197R166-1-GP  [HOLE197R166]  80.9 61.02 0 top
HCPU4  HOLE197R166-1-GP  [HOLE197R166]  138.27 61.02 0 top
HDA27  ALC3246-CG-GP-U  [QFN48J6-G465H40]  23.93 11.82 0 top
HDD1  STAR-CON30-9-GP  [111H30-100000-G4-R]  262.9 21.5 180 bottom
HDMI1  SKT-HDMI23-92-GP  [SKT-HDMI23-188137]  4.05 69.15 90 bottom
HGPU1  STF237R128H44-GP  [STF237R128H44]  150.8 95.88 0 top
HGPU2  STF237R128H44-GP  [STF237R128H44]  203.04 95.88 0 top
HGPU3  STF237R128H44-GP  [STF237R128H44]  176.92 50.64 0 top
HPMIC1  AUDIO-JK577-GP  [AJ3R2D-Y150-412]  3.8 12.1 90 bottom
IOBD3  ACES-CON18-6-GP  [51653-0180N-001]  283.9 33.8 270 bottom
IOBD4  HRS-CON16-2-GP  [TF31-16S-0D5SH-800]  196.08 50.65 270 bottom
IRCCD1  ACES-CON6-19-GP-U  [50208-0060N-001]  68.4 92 90 bottom
KB1  ACES-CON30-10-GP  [FL4S030HT6R300-DT]  191.9 27.5 270 top
KBC24  MEC1404-NU-GP  [TQFP128-2H48]  208.91 28.94 270 top
KBLIT1  PTWO-CON4-17-GP  [196503-04031-3]  189.9 50.5 90 top
L3101  IND-4D7UH-300-GP-U  [L3030-3009-2H40]  50.01 90 180 top
L8001  MMZ1005S241C-GP  [L402H22]  202.31 89.77 90 bottom
L8002  BLM15BD121SN1D-GP  [L402H22]  202.31 91.04 90 bottom
L8003  BLM15BD121SN1D-GP  [L402H22]  162.89 80.63 0 bottom
LCD1  STAR-CON40-GP  [LVD-A40SFYG]  49.9 77.5 180 bottom
LCD2  STF236R128H101-4-GP  [STF236R128H101]  32.42 77.5 180 bottom
LEDBD1  PTWO-CON6-21-GP  [196415-06031-3]  214.9 14 0 top
LIDSW1  S-5712ACDL1-M3T1U-GP  [SOT23-2D8-123H52]  154.9 117.84 0 top
LOM31  RTL8111HSD-CGT-1-GP  [QFN32J4-G2D85H36]  44.2 94.98 270 bottom
MESW1  SW-SLIDE6P-6-GP  [JSD1210-0111FC]  209.9 114.5 90 top
NOREF  -  [unnamed]  7.5 3.2 0 top
NOREF#2  -  [#2]  0 5.7 0 top
NOREF#3  -  [unnamed]  49.9 85.5 0 top
NOREF#4  -  [#2]  219.96 44.18 0 top
NOREF#5  *  [unnamed]  87.76 57.77 0 top
NOREF#6  *  [unnamed]  -1.14 0.62 0 top
NOREF#7  *  [unnamed]  15.37 97.9 0 top
NOREF#8  *  [unnamed]  284.35 49.01 0 top
NOREF#9  *  [unnamed]  222.28 130.21 0 top
NOREF#10  -  [unnamed]  219.25 127.7 0 top
NOREF#11  -  [unnamed]  173.9 123 0 top
NOREF#12  -  [#2]  143.26 98.54 0 top
NOREF#13  *  [unnamed]  188.72 7.86 0 top
NOREF#14  -  [unnamed]  111.9 123 0 top
NOREF#15  -  [#2]  0 5.7 0 top
NOREF#16  -  [#2]  106.81 38.09 0 top
NOREF#17  *  [unnamed]  280.74 0.78 0 top
NOREF#18  -  [#2]  0 5.7 0 top
NOREF#19  *  [unnamed]  199.67 116.93 0 top
NOREF#20  -  [#2]  137.03 29.2 0 top
NOREF#21  -  [unnamed]  278.1 7.43 0 top
NOREF#22  -  [#2]  292.35 4.81 90 top
NOREF#23  -  [#2]  85.34 26.02 0 top
NOREF#24  *  [unnamed]  227.58 6.08 0 top
NOREF#25  *  [unnamed]  12.95 4.94 0 top
NOREF#26  *  [unnamed]  218.82 55.48 0 top
NOREF#27  *  [unnamed]  197.23 84.31 0 top
NOREF#28  *  [unnamed]  76.58 57.01 0 top
NOREF#29  -  [#2]  255.27 -0.78 0 top
NOREF#30  -  [unnamed]  7.06 127.59 0 top
NOREF#31  *  [unnamed]  0.89 127.49 0 top
NOREF#32  -  [#2]  219.46 110.09 0 top
NOREF#33  *  [unnamed]  240.79 36.18 0 top
NOREF#34  *  [unnamed]  155.45 43.55 0 top
NOREF#35  -  [#2]  0 5.7 0 top
NOREF#36  -  [#2]  64.52 123.94 0 top
NOREF#37  -  [#2]  5 134.5 0 top
NOREF#38  -  [#2]  0 5.7 0 top
NOREF#39  -  [#2]  -5.97 117.59 270 top
NOREF#40  -  [#2]  164.54 64.02 0 top
NOREF#41  -  [#2]  2.5 0 0 top
NOREF#42  -  [#2]  -40.51 -42.18 0 top
NOREF#43  -  [#2]  267.72 6.59 0 top
NOREF#44  *  [unnamed]  27.3 24.12 0 top
NOREF#45  *  [unnamed]  153.29 100.44 0 top
NOREF#46  -  [unnamed]  270.1 55.56 0 top
NOREF#47  -  [#2]  20.95 110.86 0 top
NOREF#48  -  [#2]  68.07 124.32 180 bottom
NOREF#49  *  [unnamed]  47.27 123.33 180 bottom
NOREF#50  -  [#2]  107.72 49.18 180 bottom
NOREF#51  *  [unnamed]  0.89 127.49 180 bottom
NOREF#52  *  [unnamed]  222.28 130.21 180 bottom
NOREF#53  *  [unnamed]  129.41 122.92 180 bottom
NOREF#54  *  [unnamed]  89.27 51.86 180 bottom
NOREF#55  *  [unnamed]  188.98 59.42 180 bottom
NOREF#56  *  [unnamed]  199.9 111.24 180 bottom
NOREF#57  -  [#2]  141.99 98.28 180 bottom
NOREF#58  *  [unnamed]  195.25 89.6 180 bottom
NOREF#59  -  [#2]  159.05 7.68 180 bottom
NOREF#60  -  [#2]  635.83 8.13 180 bottom
NOREF#61  *  [unnamed]  151.13 105.01 180 bottom
NOREF#62  -  [#2]  272.92 2.91 180 bottom
NOREF#63  *  [unnamed]  4.27 4.46 180 bottom
NOREF#64  -  [#2]  235.36 7.05 180 bottom
NOREF#65  *  [unnamed]  274.57 41.48 180 bottom
NOREF#66  *  [unnamed]  280.74 0.78 180 bottom
NOREF#67  -  [#2]  219.33 120.64 180 bottom
NOREF#68  *  [unnamed]  103.25 97.14 180 bottom
NOREF#69  -  [#2]  626.67 7.33 180 bottom
NOREF#70  -  [#2]  16.89 124.57 180 bottom
NOREF#71  -  [#2]  128.52 32.37 270 bottom
NOREF#72  -  [#2]  261.72 -0.7 180 bottom
NOREF#73  -  [#2]  633.33 2.43 180 bottom
NOREF#74  *  [unnamed]  -1.14 0.62 180 bottom
NOREF#75  -  [#2]  626.67 7.33 180 bottom
PC1001  SC22U6D3V3MX-1-GP  [C603H40]  118.14 102.98 90 bottom
PC1002  SC22U6D3V3MX-1-GP  [C603H40]  112.06 76.03 90 top
PC1003  SC22U6D3V3MX-1-GP  [C603H40]  129.29 111.24 90 top
PC1004  SC22U6D3V3MX-1-GP  [C603H40]  129.29 109.97 90 top
PC1005  SC22U6D3V3MX-1-GP  [C603H40]  107.57 76.29 270 top
PC1006  SC22U6D3V3MX-1-GP  [C603H40]  117.88 101.55 270 top
PC1007  SC22U6D3V3MX-1-GP  [C603H40]  107.57 75.02 270 top
PC1008  SC22U6D3V3MX-1-GP  [C603H40]  107.57 80.1 270 top
PC1009  SC22U6D3V3MX-1-GP  [C603H40]  129.29 106.16 90 top
PC1010  SC22U6D3V3MX-1-GP  [C603H40]  129.29 107.43 90 top
PC1011  SC22U6D3V3MX-1-GP  [C603H40]  129.29 109.08 270 bottom
PC1012  SC22U6D3V3MX-1-GP  [C603H40]  129.29 105.01 270 bottom
PC1013  SC22U6D3V3MX-1-GP  [C603H40]  112.06 73.49 90 top
PC1014  SC22U6D3V3MX-1-GP  [C603H40]  107.57 78.83 270 top
PC1015  SC22U6D3V3MX-1-GP  [C603H40]  129.29 107.68 270 bottom
PC1016  SC22U6D3V3MX-1-GP  [C603H40]  129.29 106.28 270 bottom
PC1017  SC22U6D3V3MX-1-GP  [C603H40]  129.29 104.89 90 top
PC1018  SC22U6D3V3MX-1-GP  [C603H40]  129.29 108.7 90 top
PC1019  SC22U6D3V3MX-1-GP  [C603H40]  112.06 74.76 90 top
PC1020  SC22U6D3V3MX-1-GP  [C603H40]  118.87 110.86 270 top
PC1021  SC22U6D3V3MX-1-GP  [C603H40]  112.04 79.89 90 top
PC1022  SC22U6D3V3MX-1-GP  [C603H40]  112.04 78.6 90 top
PC1023  SC22U6D3V3MX-1-GP  [C603H40]  118.87 104.13 270 top
PC1024  SC22U6D3V3MX-1-GP  [C603H40]  118.87 109.46 270 top
PC1025  SC22U6D3V3MX-1-GP  [C603H40]  129.29 110.48 270 bottom
PC1026  SC22U6D3V3MX-1-GP  [C603H40]  107.57 73.75 270 top
PC1027  SC22U6D3V3MX-1-GP  [C603H40]  118.87 108.06 270 top
PC1028  SC22U6D3V3MX-1-GP  [C603H40]  118.87 106.67 270 top
PC1029  SC22U6D3V3MX-1-GP  [C603H40]  118.87 105.4 270 top
PC1030  SC22U6D3V3MX-1-GP  [C603H40]  118.87 102.86 270 top
PC1031  SC22U6D3V3MX-1-GP  [C603H40]  106.15 100.92 270 top
PC1032  SC22U6D3V3MX-1-GP  [C603H40]  91.01 72.02 270 top
PC1033  SC22U6D3V3MX-1-GP  [C603H40]  75.79 73.21 90 bottom
PC1034  SC22U6D3V3MX-1-GP  [C603H40]  91.01 73.31 270 top
PC1035  SC22U6D3V3MX-1-GP  [C603H40]  164.72 66.03 0 bottom
PC1036  SC22U6D3V3MX-1-GP  [C603H40]  166.12 66.03 0 bottom
PC1037  SC22U6D3V3MX-1-GP  [C603H40]  160.27 63.23 180 bottom
PC1038  SC22U6D3V5MX-2GP  [C805H58]  146.25 83.96 180 bottom
PC1039  SC22U6D3V5MX-2GP  [C805H58]  144.4 83.96 180 bottom
PC1041  SC22U6D3V3MX-1-GP  [C603H40]  102.95 78.85 90 top
PC1042  SC22U6D3V3MX-1-GP  [C603H40]  102.95 80.15 90 top
PC1043  SC22U6D3V3MX-1-GP  [C603H40]  106.88 99.63 270 top
PC1044  SC22U6D3V3MX-1-GP  [C603H40]  104.78 74.41 180 top
PC1046  SC22U6D3V3MX-1-GP  [C603H40]  138.3 103.24 270 bottom
PC1047  SC22U6D3V3MX-1-GP  [C603H40]  132.72 103.24 90 bottom
PC1048  SC22U6D3V3MX-1-GP  [C603H40]  117.12 73.9 180 top
PC1049  SC22U6D3V3MX-1-GP  [C603H40]  115.19 79.61 0 top
PC1050  SC22U6D3V3MX-1-GP  [C603H40]  132.72 105.78 270 top
PC1051  SC22U6D3V3MX-1-GP  [C603H40]  132.72 104.51 90 bottom
PC1052  SC22U6D3V3MX-1-GP  [C603H40]  138.3 104.51 270 bottom
PC1053  SC22U6D3V3MX-1-GP  [C603H40]  138.3 103.24 90 top
PC1054  SC22U6D3V3MX-1-GP  [C603H40]  116.59 85.33 180 top
PC1055  SC10U6D3V3MX-GP  [C603H38]  91.44 11.29 0 top
PC1056  SC10U6D3V3MX-GP  [C603H38]  140.08 19.8 0 top
PC1057  SC10U6D3V3MX-GP  [C603H38]  129.54 19.67 0 top
PC1058  SC10U6D3V3MX-GP  [C603H38]  84.33 50.02 270 top
PC1061  SC10U6D3V3MX-GP  [C603H38]  94.08 65.24 270 top
PC1064  SC22U6D3V5MX-2GP  [C805H58]  84.22 51.93 270 top
PC1065  SC22U6D3V3MX-1-GP  [C603H40]  113.31 81.9 90 top
PC1066  SC22U6D3V3MX-1-GP  [C603H40]  132.72 103.24 270 top
PC1067  SC22U6D3V3MX-1-GP  [C603H40]  113.92 79.61 0 top
PC1068  SC22U6D3V3MX-1-GP  [C603H40]  115.85 73.9 180 top
PC1069  SC22U6D3V3MX-1-GP  [C603H40]  113.92 100.19 90 top
PC1070  SC22U6D3V3MX-1-GP  [C603H40]  113.92 104.38 90 top
PC1071  SC22U6D3V3MX-1-GP  [C603H40]  113.92 105.78 90 top
PC1072  SC22U6D3V3MX-1-GP  [C603H40]  90.5 74.58 270 top
PC1073  SC22U6D3V3MX-1-GP  [C603H40]  102.74 99.55 180 top
PC1074  SC22U6D3V3MX-1-GP  [C603H40]  90.04 75.88 270 top
PC1075  SC22U6D3V3MX-1-GP  [C603H40]  106.15 103.49 270 top
PC1076  SC22U6D3V3MX-1-GP  [C603H40]  95.58 70.95 90 top
PC1077  SC22U6D3V3MX-1-GP  [C603H40]  90.04 79.69 270 top
PC1078  SC22U6D3V3MX-1-GP  [C603H40]  89.92 81.39 270 top
PC1079  SC22U6D3V3MX-1-GP  [C603H40]  92.01 70.18 0 top
PC1080  SC22U6D3V3MX-1-GP  [C603H40]  106.15 102.22 270 top
PC1081  SC22U6D3V3MX-1-GP  [C603H40]  98.68 71.59 0 top
PC1082  SC22U6D3V3MX-1-GP  [C603H40]  75.82 71.49 90 bottom
PC1083  SC22U6D3V3MX-1-GP  [C603H40]  107.95 106.67 180 top
PC1084  SC22U6D3V3MX-1-GP  [C603H40]  113.92 102.98 90 top
PC1085  SC22U6D3V3MX-1-GP  [C603H40]  101.35 99.55 180 top
PC1086  SC22U6D3V3MX-1-GP  [C603H40]  104.14 99.55 180 top
PC1087  SC22U6D3V3MX-1-GP  [C603H40]  90.04 78.42 270 top
PC1088  SC22U6D3V3MX-1-GP  [C603H40]  97.41 71.59 0 top
PC1089  SC22U6D3V3MX-1-GP  [C603H40]  102.95 77.56 90 top
PC1090  SC22U6D3V3MX-1-GP  [C603H40]  90.04 77.15 270 top
PC1091  SC22U6D3V3MX-1-GP  [C603H40]  75.79 74.48 90 bottom
PC1092  SC22U6D3V3MX-1-GP  [C603H40]  102.95 76.26 90 top
PC1093  SC22U6D3V3MX-1-GP  [C603H40]  106.15 104.76 270 top
PC1094  SC22U6D3V3MX-1-GP  [C603H40]  75.82 76.36 90 bottom
PC1095  SC22U6D3V3MX-1-GP  [C603H40]  113.92 101.59 90 top
PC1096  SC22U6D3V3MX-1-GP  [C603H40]  103.5 74.41 180 top
PC1097  SC22U6D3V3MX-1-GP  [C603H40]  132.72 104.51 270 top
PC1098  SC22U6D3V3MX-1-GP  [C603H40]  138.3 104.51 90 top
PC4301  SC1U50V3KX-GP  [C603H32]  59.05 107.17 0 top
PC4302  SCD1U50V3KX-GP  [C603H36]  63.22 112.56 180 top
PC4303  SCD01U50V2KX-1GP  [C402H22]  68.67 112.66 180 top
PC4304  SCD01U50V2KX-1GP  [C402H22]  67.86 112.66 180 top
PC4305  SCD01U50V2KX-1GP  [C402H22]  67.04 112.66 180 top
PC4306  SC10U25V5KX-GP  [C805H56]  65.62 112.76 180 top
PC4401  SC2D2U10V3KX-1GP  [C603H36]  228.98 19.04 0 top
PC4402  SCD1U25V2KX-GP  [C402H22]  231.91 10.53 90 top
PC4403  SCD1U25V2KX-GP  [C402H22]  232.74 12.23 270 top
PC4404  SCD1U25V2KX-GP  [C402H22]  230.94 12.25 90 top
PC4405  SC10U25V5KX-GP  [C805H56]  222.79 20.69 90 top
PC4407  SC10U25V5KX-GP  [C805H56]  222.78 22.5 90 top
PC4409  SCD1U50V3KX-GP  [C603H36]  222.5 22.72 270 bottom
PC4410  SC2200P50V2KX-2GP  [C402H22]  222.76 24.75 270 bottom
PC4411  SCD1U25V2KX-GP  [C402H22]  222.76 23.86 270 bottom
PC4412  SC1U50V3KX-GP  [C603H32]  228.98 13.52 90 top
PC4413  SCD01U50V2KX-1GP  [C402H22]  238.89 11.59 0 top
PC4414  SCD047U25V2KX-GP  [C402H22]  228.22 16.83 0 top
PC4415  SC10U25V5KX-GP  [C805H56]  231.65 32.24 270 bottom
PC4416  SC10U25V5KX-GP  [C805H56]  230.5 26.27 90 top
PC4417  SC10U25V5KX-GP  [C805H56]  231.65 30.34 270 bottom
PC4418  SC10U25V5KX-GP  [C805H56]  231.65 34.15 270 bottom
PC4419  SCD1U50V3KX-GP  [C603H36]  231.65 30.85 90 top
PC4420  SCD1U25V2KX-GP  [C402H22]  232.79 22.79 90 top
PC4421  SCD1U25V2KX-GP  [C402H22]  230.89 22.79 270 top
PC4422  SCD1U25V2KX-GP  [C402H22]  234.49 22.79 90 top
PC4423  SC100P50V2JN-L-GP  [C402H22]  241.94 13.12 90 top
PC4424  SC100P50V2JN-L-GP  [C402H22]  241.94 14.13 90 top
PC4426  SC1U50V3KX-GP  [C603H32]  245.24 10.91 90 top
PC4501  SC4D7U25V5KX-L2-GP  [C805H58]  41.33 43.29 0 bottom
PC4502  SC4D7U25V5KX-L2-GP  [C805H58]  39.5 43.29 0 bottom
PC4503  SCD1U50V3KX-L-GP  [C603H36]  51.13 47.8 180 top
PC4504  SCD1U16V2KX-L-GP  [C402H22]  26.92 41.01 0 top
PC4505  SC68P50V2JN-1GP  [C402H22]  53.11 47.44 180 top
PC4506  SC18P50V2JN-1-GP  [C402H22]  56.44 44.21 270 top
PC4507  SC10U25V5KX-L-GP  [C805H56]  43.81 45.58 270 top
PC4508  SCD1U16V2KX-L-GP  [C402H22]  53 38.55 0 top
PC4509  SCD1U50V3KX-L-GP  [C603H36]  51.89 38.4 180 top
PC4510  SC4D7U25V5KX-L2-GP  [C805H58]  56.79 42.86 90 top
PC4511  SC4D7U25V5KX-L2-GP  [C805H58]  47.75 42.91 270 top
PC4512  SCD1U50V3KX-L-GP  [C603H36]  41.4 35.16 0 top
PC4513  SC10U25V5KX-L-GP  [C805H56]  44.96 35.29 0 top
PC4514  SC10U25V5KX-L-GP  [C805H56]  43.05 35.29 0 top
PC4515  SCD1U50V3KX-L-GP  [C603H36]  41.4 43.42 180 top
PC4516  SCD1U16V2KX-L-GP  [C402H22]  24.89 35.55 180 top
PC4517  SC18P50V2JN-1-GP  [C402H22]  56.13 38.59 180 top
PC4518  SCD1U50V3KX-L-GP  [C603H36]  48.51 45.07 180 top
PC4601  SC1500P50V2KX-2GP  [C402H22]  144.23 119.33 180 top
PC4602  SCD015U25V2KX-GP  [C402H22]  152.27 113.4 90 bottom
PC4603  SC1KP50V2KX-1GP  [C402H22]  152.27 111.62 90 bottom
PC4604  SC15P50V2JN-L-GP  [C402H22]  149.48 112.89 90 top
PC4605  SC1KP50V2KX-1GP  [C402H22]  153.54 112.13 0 bottom
PC4606  SCD015U25V2KX-GP  [C402H22]  151.26 116.7 0 bottom
PC4607  SC6800P25V2KX-1DLGP  [C402H22]  152.15 116.7 0 bottom
PC4608  SC1KP50V2KX-1GP  [C402H22]  152.27 109.84 90 bottom
PC4609  SC220P50V2KX-3GP  [C402H22]  148.18 115.78 270 top
PC4610  SCD1U25V2KX-GP  [C402H22]  150.19 123.58 0 bottom
PC4611  SC1KP50V2KX-1GP  [C402H22]  151.89 110.22 0 top
PC4612  SC2200P50V2KX-2GP  [C402H22]  149.81 109.54 270 bottom
PC4613  SC470P50V2KX-3GP  [C402H22]  146.05 116.95 0 top
PC4614  SC470P50V2KX-3GP  [C402H22]  147.65 105.43 270 top
PC4615  SC470P50V2KX-3GP  [C402H22]  147.96 111.11 0 top
PC4616  SC4700P25V2KX-4-GP  [C402H22]  146.23 119.15 90 bottom
PC4617  SC10P50V2JN-4GP  [C402H22]  146.89 107.21 270 top
PC4618  SC2200P50V2KX-2GP  [C402H22]  145.62 106.83 180 top
PC4619  SC15P50V2JN-L-GP  [C402H22]  144.27 116.95 0 top
PC4620  SC100P50V2JN-L-GP  [C402H22]  145.96 107.2 90 bottom
PC4621  SC820P50V2KX-1-DL-GP  [C402H22]  145.96 108.09 90 bottom
PC4622  SC1KP50V2KX-1GP  [C402H22]  144.93 120.38 180 bottom
PC4623  SCD047U25V2KX-GP  [C402H22]  144.01 108.16 270 top
PC4625  SC1KP50V2KX-1GP  [C402H22]  142.6 119 90 bottom
PC4626  SCD01U50V2KX-1GP  [C402H22]  146.18 111.11 180 top
PC4627  SC1KP50V2KX-1GP  [C402H22]  141.35 119.43 0 bottom
PC4628  SCD1U25V2KX-GP  [C402H22]  142.88 117.33 90 top
PC4629  SCD01U50V2KX-1GP  [C402H22]  143.51 110.09 90 top
PC4630  SCD1U25V2KX-GP  [C402H22]  145.29 111.11 180 top
PC4631  SC1U10V2KX-1GP  [C402H22]  143.51 110.98 90 top
PC4632  SC1KP50V2KX-1GP  [C402H22]  149.48 113.78 270 top
PC4633  SC1KP50V2KX-1GP  [C402H22]  145.16 116.95 0 top
PC4634  SCD022U16V2KX-3GP  [C402H22]  146.23 120.04 90 bottom
PC4702  SC10U25V5KX-10-GP  [C805H58]  120.95 120.38 0 top
PC4703  SC10U25V5KX-10-GP  [C805H58]  117.68 122.87 270 top
PC4704  SC10U25V5KX-10-GP  [C805H58]  117.35 120.38 0 top
PC4705  SC10U25V5KX-10-GP  [C805H58]  119.15 120.38 0 top
PC4706  SCD22U25V3KX-GP  [C603H40]  125.4 123.84 180 bottom
PC4707  SC2D2U10V3KX-L-GP  [C603H36]  128.72 116.37 270 bottom
PC4708  SC1U10V2KX-1GP  [C402H22]  128.93 118.4 270 bottom
PC4709  SC2200P50V2KX-2GP  [C402H22]  119 116.06 270 bottom
PC4710  SCD1U25V2KX-GP  [C402H22]  120.75 121.8 90 bottom
PC4802  SC10U25V5KX-GP  [C805H56]  102.87 123.45 180 top
PC4803  SC10U25V5KX-GP  [C805H56]  104.7 123.45 180 top
PC4804  SC10U25V5KX-GP  [C805H56]  107.31 119.62 90 bottom
PC4805  SC10U25V5KX-GP  [C805H56]  107.31 121.52 90 bottom
PC4806  SC10U25V5KX-GP  [C805H56]  108.03 116.95 0 top
PC4807  SC2D2U10V3KX-L-GP  [C603H36]  116.13 112.86 90 top
PC4808  SC1U10V2KX-1GP  [C402H22]  116.41 114.29 270 bottom
PC4809  SCD22U25V3KX-GP  [C603H40]  111.61 119.64 180 bottom
PC4810  SC2200P50V2KX-2GP  [C402H22]  107.06 112.63 0 bottom
PC4811  SCD1U25V2KX-GP  [C402H22]  106.76 118.2 90 bottom
PC5001  SC2D2U10V3KX-1GP  [C603H36]  144.1 122.14 270 bottom
PC5002  SCD1U25V2KX-GP  [C402H22]  135.41 119.75 270 bottom
PC5008  SCD22U25V3KX-GP  [C603H40]  137.79 123.3 180 bottom
PC5027  SC10U25V5KX-GP  [C805H56]  134.9 123.86 270 bottom
PC5029  SC10U25V5KX-GP  [C805H56]  134.9 121.96 270 bottom
PC5031  SC2200P50V2KX-2GP  [C402H22]  135.51 118.48 0 bottom
PC5104  SC22U6D3V5MX-L3-GP  [C805H58]  72.26 57.64 270 bottom
PC5105  SC22U6D3V5MX-L3-GP  [C805H58]  67.82 57.64 90 bottom
PC5107  SC22U6D3V5MX-L3-GP  [C805H58]  67.82 57.64 270 top
PC5109  SC22U6D3V5MX-L3-GP  [C805H58]  72.26 57.64 90 top
PC5110  SC1U10V2KX-L1-GP  [C402H22]  64.42 63.98 0 top
PC5111  SC10U25V5KX-L-GP  [C805H56]  62.99 72.25 180 top
PC5112  SC2D2U10V3KX-L-GP  [C603H36]  65.56 64.21 0 top
PC5113  SC470P50V2KX-L-GP  [C402H22]  62.72 63.95 180 top
PC5114  SCD1U25V2KX-L-GP  [C402H22]  66.95 70.36 0 top
PC5115  SC10U25V5KX-L-GP  [C805H56]  61.09 72.25 180 top
PC5116  SCD1U25V2KX-L-GP  [C402H22]  58.9 69.1 0 top
PC5118  SCD1U16V2KX-3GP  [C402H22]  72.03 56.27 90 top
PC5119  SCD1U16V2KX-3GP  [C402H22]  63.32 47.13 270 top
PC5120  SCD1U16V2KX-3GP  [C402H22]  62.05 46.72 0 top
PC5121  SC1U10V2KX-1GP  [C402H22]  65.4 50.16 180 top
PC5122  SC10U6D3V3MX-GP  [C603H38]  65.53 52.94 0 top
PC5123  SCD1U16V2KX-3GP  [C402H22]  60.33 49.77 180 top
PC5124  SC22U6D3V5MX-2GP  [C805H58]  59.69 54.72 180 top
PC5301  SC22U6D3V5MX-L3-GP  [C805H58]  35.18 23.23 270 top
PC5302  SC4D7U25V5KX-L2-GP  [C805H58]  45.09 22.97 270 top
PC5303  SC22U6D3V5MX-L3-GP  [C805H58]  39.75 23.23 90 top
PC5304  SCD1U25V2KX-L-GP  [C402H22]  42.55 24.62 90 top
PC5305  SC22U6D3V5MX-L3-GP  [C805H58]  35.17 21.35 270 top
PC5306  SC22U6D3V5MX-L3-GP  [C805H58]  39.74 21.35 90 top
PC5307  SCD1U25V2KX-L-GP  [C402H22]  43.92 31.91 270 top
PC5308  SC10U25V5KX-L-GP  [C805H56]  49.28 33.43 90 top
PC5309  SC10U25V5KX-L-GP  [C805H56]  49.28 31.61 90 top
PC5310  SC220P50V2KX-3GP  [C402H22]  50.55 29.32 270 top
PC5311  SCD01U50V2KX-L-GP  [C402H22]  47.75 25.39 90 top
PC5401  SC100P50V2JN-7-GP  [C402H22]  55.85 8.21 270 bottom
PC5402  SC10U6D3V3MX-GP  [C603H38]  63.25 8.77 270 bottom
PC5403  SC10U6D3V3MX-GP  [C603H38]  50.04 4.68 90 bottom
PC5404  SC10U6D3V3MX-GP  [C603H38]  63.25 7.5 270 bottom
PC5405  SC100P50V2JN-7-GP  [C402H22]  62.71 4.71 0 bottom
